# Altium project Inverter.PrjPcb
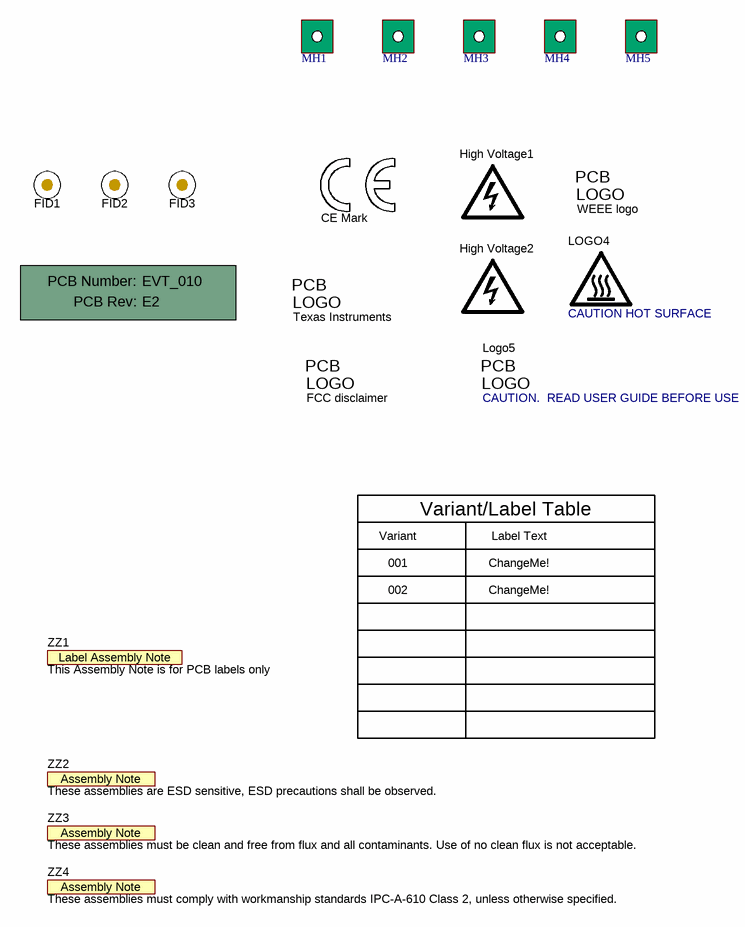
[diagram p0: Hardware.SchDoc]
TID: N/A; TechSupport: http://www.ti.com/support; SCH_Rev: E2; PRJ_Title: SiC Inverter Main Board; PRJ_Number: EVT_010; PRJ_Engineer: Ramesh Ramamoorthy; PRJ_Customer: EV Traction; PCB_Rev: E2; PCB_Layout: Ramesh Ramamoorthy; CopyrightYear: 2020
2 sheets, 92 parts. Net scope: global (net labels, ports and power ports of the same name join across sheets).
Board file: inverter_r7.PcbDoc
Sheets:
  Hardware.SchDoc
  inverter_r5.SchDoc

## Sheet Hardware.SchDoc
size 431 x 279 mm; Date: Not shown in title block; ApprovedBy: Not shown in title block; CheckedBy: Not shown in title block; Author: Not shown in title block; CompanyName: Not shown in title block; Engineer: Not shown in title block; Organization: Not shown in title block; Address1: Not shown in title block; Address2: Not shown in title block; Address3: Not shown in title block; Address4: Not shown in title block; DocumentNumber: 3; Revision: Use project parameter SCH_Rev; SheetNumber: 3; SheetTotal: 3; PageSetup: Record=PageOptions¦CenterHorizontal=True¦CenterVertical=True¦PrintScale=1.00¦XCorrection=1.00¦YCorrection=1.00¦PrintKind=0¦BorderSize=5000000¦LeftOffset=0¦BottomOffset=0¦Orientation=2¦PaperLength=1000¦PaperWidth=1000¦Scale=100¦PaperSource=15¦PrintQuality=600¦MediaType=1¦DitherType=10¦PaperKind=Letter¦PrintScaleMode=1

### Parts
!PCB1  Printed Circuit Board  (value not drawn)  (mechanical)
FID1  Fiducial  [Fiducial10-20]  (value not drawn)
FID2  Fiducial  [Fiducial10-20]  (value not drawn)
FID3  Fiducial  [Fiducial10-20]  (value not drawn)
High_Voltage1  DANGER HIGH VOLTAGE  [IEC_HighVoltage_Small]  (value not drawn)  (no BOM)
High_Voltage2  DANGER HIGH VOLTAGE  [IEC_HighVoltage_Small]  (value not drawn)  (no BOM)
Logo1  Texas Instruments  [TI_Stacked_Overlay_Medium]  (no BOM)
Logo2  CE Mark  [CE_Mark_5mm]  (no BOM)
Logo3  WEEE logo  [WEEE_Minimum]  (no BOM)
LOGO4  CAUTION HOT SURFACE  [IEC_HotSurface_Small]  (no BOM)
Logo5  CAUTION.  READ USER GUIDE BEFORE USE  [IEC_Caution_Small]  (no BOM)
Logo6  FCC disclaimer  [FCC_disclaimer]  (no BOM)
MH1  MTG_NoPads  [MTG_159mil]  (value not drawn)  (no BOM)
MH2  MTG_NoPads  [MTG_159mil]  (value not drawn)  (no BOM)
MH3  MTG_NoPads  [MTG_159mil]  (value not drawn)  (no BOM)
MH4  MTG_NoPads  [MTG_159mil]  (value not drawn)  (no BOM)
MH5  MTG_NoPads  [MTG_159mil]  (value not drawn)  (no BOM)
ZZ1  This Assembly Note is for PCB labels only  [AssemblyNoteLabel]  (no BOM)
ZZ2  These assemblies are ESD sensitive, ESD precautions shall be observed.  [AssemblyNote]  (no BOM)
ZZ3  These assemblies must be clean and free from flux and all contaminants. Use of no clean flux is not acceptable.  [AssemblyNote]  (no BOM)
ZZ4  These assemblies must comply with workmanship standards IPC-A-610 Class 2, unless otherwise specified.  [AssemblyNote]  (no BOM)

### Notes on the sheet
- Variant
- Variant/Label Table
- Label Text
- 001
- 002
- ChangeMe!

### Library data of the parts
!PCB1 = CMP-0003618-2: Manufacturer: Any; PartNumber: EVT_010
FID1-FID3 = CMP-0077181-1: Fiducial mark.  There is nothing to buy or mount.
High_Voltage1 High_Voltage2 = CMP-0074835-1: IEC 61010-1 High Voltage Warning; SymbolCreator: a0412235
Logo1 = CMP-0074838-1: Texas Instrument Corporate Signature; SymbolCreator: a0412235; Lib Reference: TI_Logo; Library Reference: Logo
Logo2 = CMP-0074844-1: SymbolCreator: a0412235
Logo3 = CMP-0074769-1
LOGO4 = CMP-0074837-1: IEC 61010-1 Hot Surface Warning; SymbolCreator: a0412235
Logo5 = CMP-0074836-1: IEC 61010-1 Caution Warning; SymbolCreator: a0412235; Lib Reference: IEC_Caution
Logo6 = CMP-0074847-1: FCC_disclaimer; Library Reference: Logo
MH1-MH5 = CMP-0078424-2: PCB Mounting Hole, No Pad; Manufacturer: Any; Key: Mounting Hole (non-standard) No Pad
ZZ1 = CMP-0003616-3
ZZ2 = CMP-0077236-1
ZZ3 = CMP-0077237-1
ZZ4 = CMP-0077238-1

## Sheet inverter_r5.SchDoc
size 431 x 279 mm; Date: Not shown in title block; ApprovedBy: Not shown in title block; CheckedBy: Not shown in title block; Author: Not shown in title block; CompanyName: Not shown in title block; Engineer: Not shown in title block; Organization: Not shown in title block; Address1: Not shown in title block; Address2: Not shown in title block; Address3: Not shown in title block; Address4: Not shown in title block; DocumentNumber: 2; Revision: Use project parameter SCH_Rev; SheetNumber: 2; SheetTotal: 3; PageSetup: Record=PageOptions¦CenterHorizontal=True¦CenterVertical=True¦PrintScale=1.00¦XCorrection=1.00¦YCorrection=1.00¦PrintKind=0¦BorderSize=5000000¦LeftOffset=0¦BottomOffset=0¦Orientation=2¦PaperLength=1000¦PaperWidth=1000¦Scale=100¦PaperSource=15¦PrintQuality=600¦MediaType=1¦DitherType=10¦PaperKind=Letter¦PrintScaleMode=1
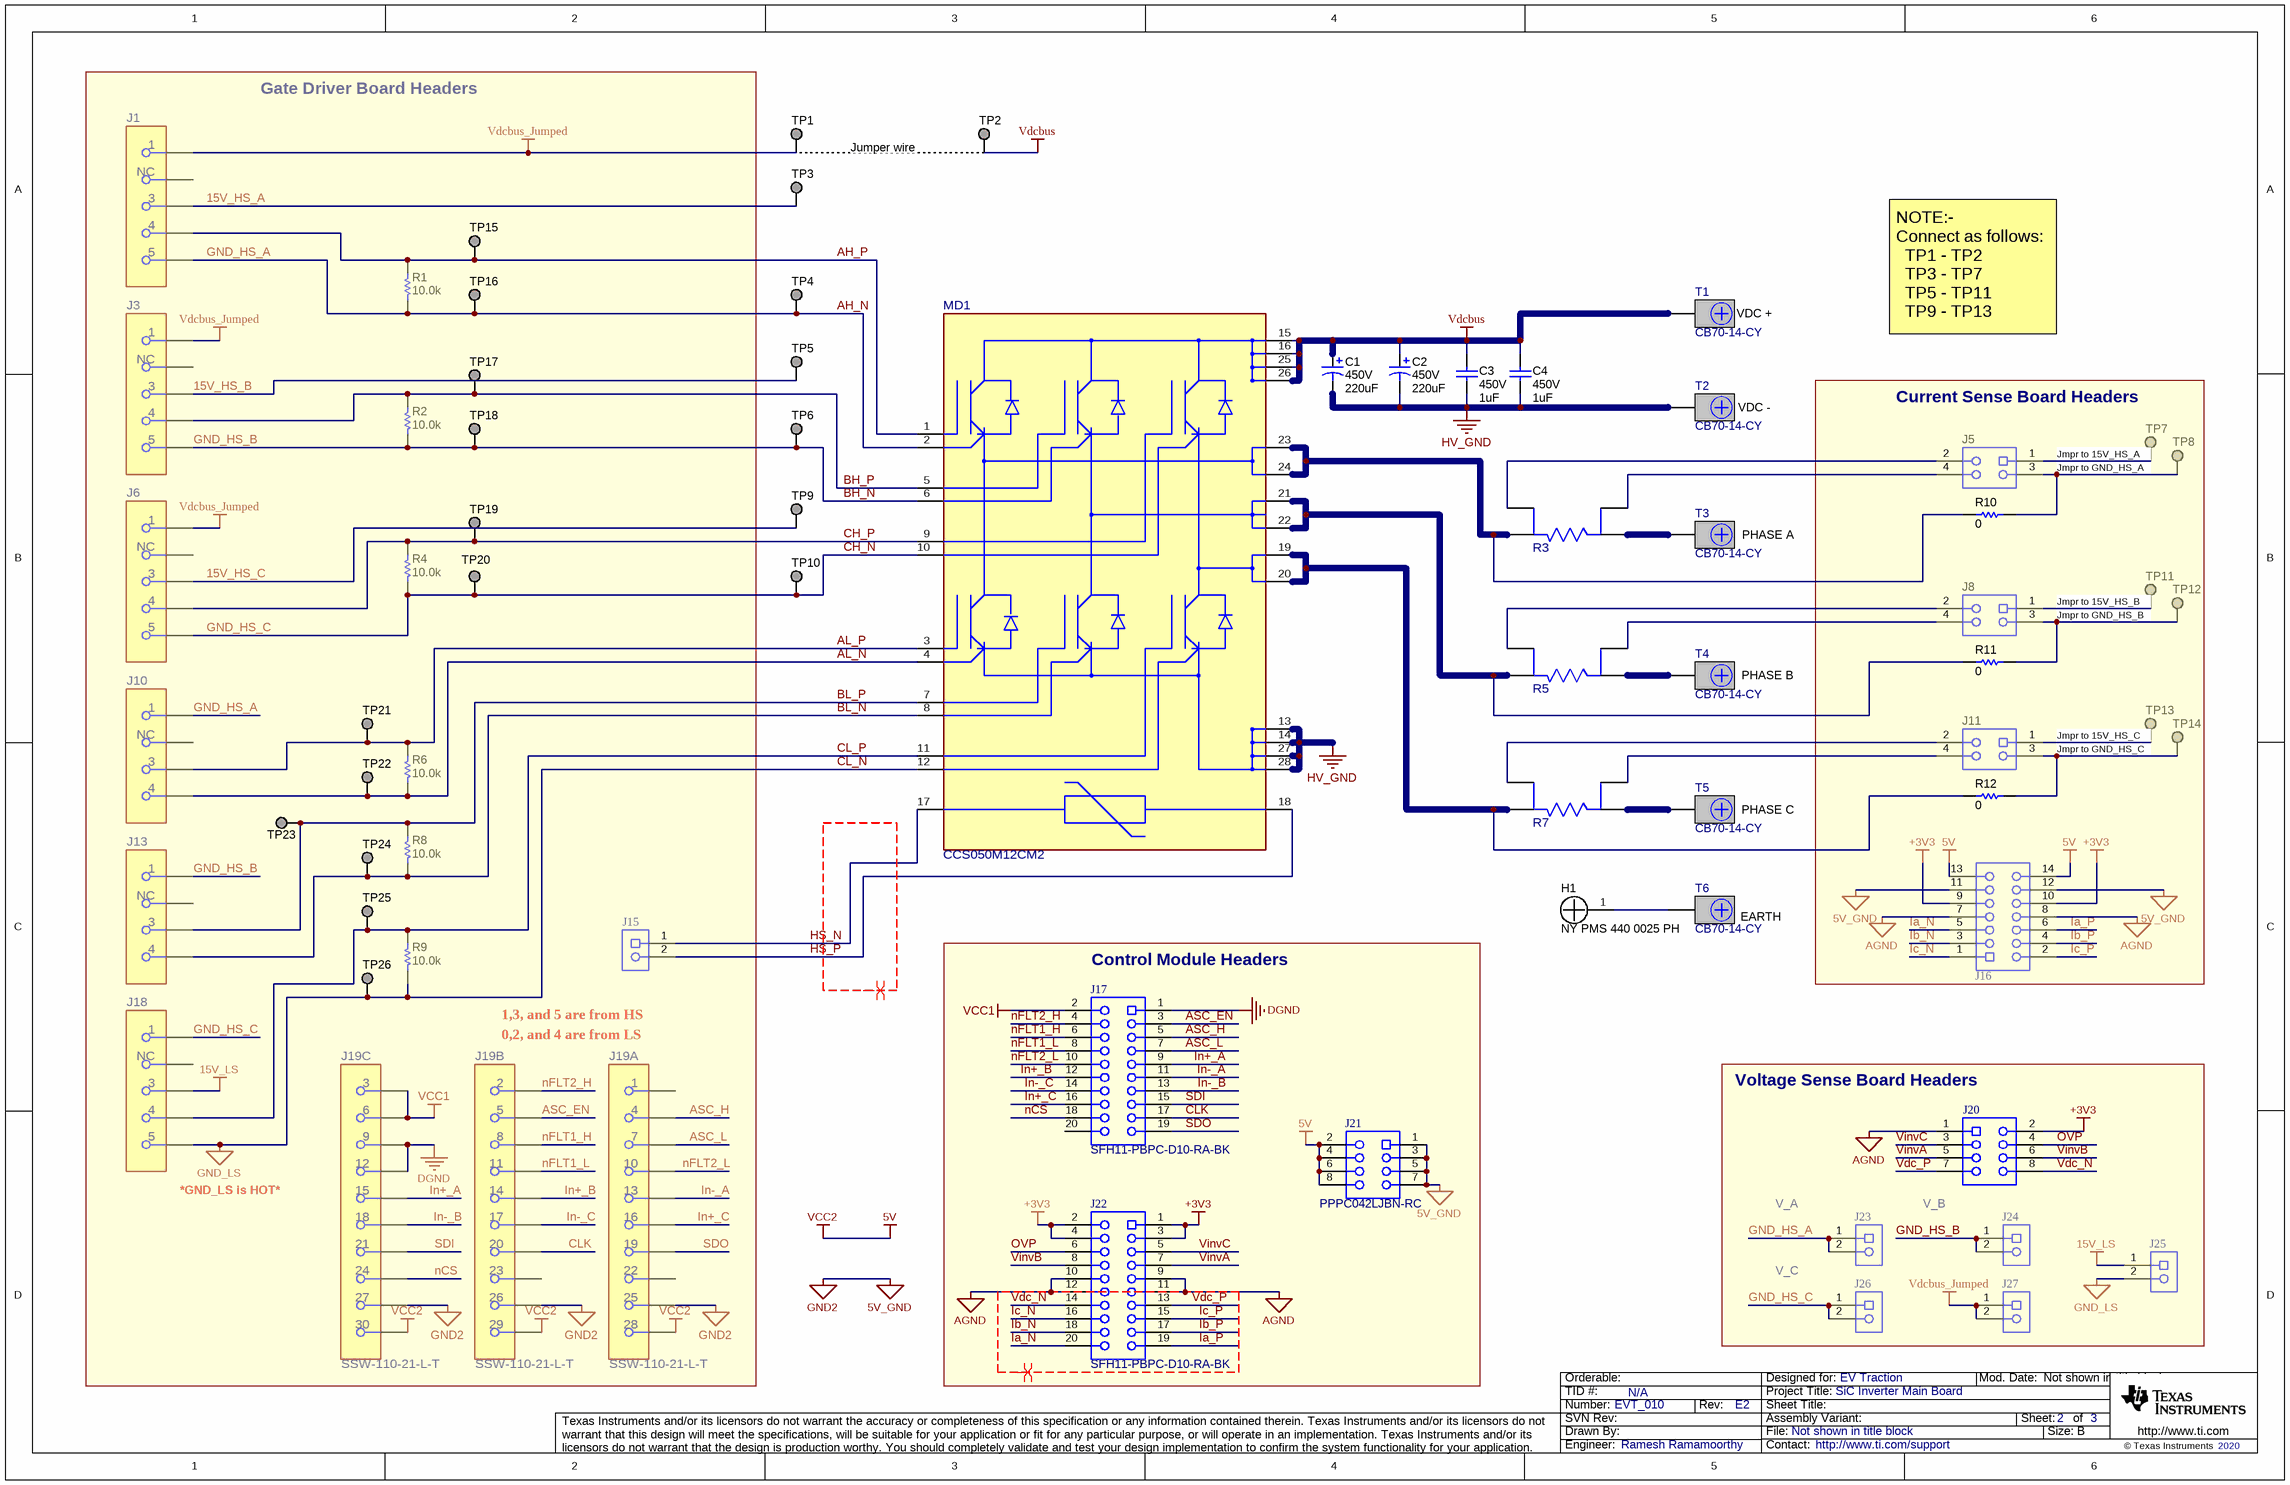
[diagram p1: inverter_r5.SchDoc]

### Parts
C1  VDC_V: 450V  ValueDisplayed: 220uF  [Nichicon_2500x4000_Snap]  (hidden comment: LLS2W221MELA)
C2  VDC_V: 450V  ValueDisplayed: 220uF  [Nichicon_2500x4000_Snap]  (hidden comment: LLS2W221MELA)
C3  VDC_V: 450V  ValueDisplayed: 1uF  [MPK_1800x950]  (hidden comment: 450MPK105J)
C4  VDC_V: 450V  ValueDisplayed: 1uF  [MPK_1800x950]  (hidden comment: 450MPK105J)
H1  NY PMS 440 0025 PH  [NY PMS 440 0025 PH]
J1  SSW-105-01-G-S-002  [FP-SSW-105-01-G-S-002_HDR4-MFG]  (value not drawn)
J3  SSW-105-01-G-S-002  [FP-SSW-105-01-G-S-002_HDR4-MFG]  (value not drawn)
J5  5-534206-2  [CONN_534206-2]  (value not drawn)
J6  SSW-105-01-G-S-002  [FP-SSW-105-01-G-S-002_HDR4-MFG]  (value not drawn)
J8  5-534206-2  [CONN_534206-2]  (value not drawn)
J10  SSW-104-01-G-S-002  [FP-SSW-104-01-G-S-002_HDR4-MFG]  (value not drawn)
J11  5-534206-2  [CONN_534206-2]  (value not drawn)
J13  SSW-104-01-G-S-002  [FP-SSW-104-01-G-S-002_HDR4-MFG]  (value not drawn)
J15  5-534206-1  [CONN_534206-1]  (value not drawn)
J16  PPPC072LFBN-RC  [Sullins_xPxC072LFBN-RC]  (value not drawn)
J17  SFH11-PBPC-D10-RA-BK  [Sullins_SFH11-xxxC-D10-RA]
J18  SSW-105-01-G-S-002  [FP-SSW-105-01-G-S-002_HDR4-MFG]  (value not drawn)
J19  SSW-110-21-L-T  [FP-SSW-110-21-L-T_HDR30-MFG]  (parts A,B,C of 3)
J20  PPPC042LFBN-RC  [CONN_PPPC042LFBN-RC]  (value not drawn)
J21  PPPC042LJBN-RC  [CONN_PPPC042LJBN-RC]
J22  SFH11-PBPC-D10-RA-BK  [Sullins_SFH11-xxxC-D10-RA]
J23  5-534206-1  [CONN_534206-1]  (value not drawn)
J24  5-534206-1  [CONN_534206-1]  (value not drawn)
J25  5-534206-1  [CONN_534206-1]  (value not drawn)
J26  5-534206-1  [CONN_534206-1]  (value not drawn)
J27  5-534206-1  [CONN_534206-1]  (value not drawn)
MD1  CCS050M12CM2  [FP-CCS050M12CM2_PTH_MODULE_107MM5_45MM-MFG]
R1  ValueDisplayed: 10.0k  [0603]  (hidden comment: CRCW060310K0FKEA)
R2  ValueDisplayed: 10.0k  [0603]  (hidden comment: CRCW060310K0FKEA)
R3  CSS4J-4026R-L500F  [FP-CSS4J-4026R-L500F_4026-MFG]  (value not drawn)
R4  ValueDisplayed: 10.0k  [0603]  (hidden comment: CRCW060310K0FKEA)
R5  CSS4J-4026R-L500F  [FP-CSS4J-4026R-L500F_4026-MFG]  (value not drawn)
R6  ValueDisplayed: 10.0k  [0603]  (hidden comment: CRCW060310K0FKEA)
R7  CSS4J-4026R-L500F  [FP-CSS4J-4026R-L500F_4026-MFG]  (value not drawn)
R8  ValueDisplayed: 10.0k  [0603]  (hidden comment: CRCW060310K0FKEA)
R9  ValueDisplayed: 10.0k  [0603]  (hidden comment: CRCW060310K0FKEA)
R10  ValueDisplayed: 0  [0805_HV]  (hidden comment: ERJ-6GEY0R00V)
R11  ValueDisplayed: 0  [0805_HV]  (hidden comment: ERJ-6GEY0R00V)
R12  ValueDisplayed: 0  [0805_HV]  (hidden comment: ERJ-6GEY0R00V)
T1  CB70-14-CY  [CB70-14-CY]
T2  CB70-14-CY  [CB70-14-CY]
T3  CB70-14-CY  [CB70-14-CY]
T4  CB70-14-CY  [CB70-14-CY]
T5  CB70-14-CY  [CB70-14-CY]
T6  CB70-14-CY  [CB70-14-CY]
TP1  TP_H0.45P0.75  [TP_H045P075]  (value not drawn)  (no BOM)
TP2  TP_H0.45P0.75  [TP_H045P075]  (value not drawn)  (no BOM)
TP3  TP_H0.45P0.75  [TP_H045P075]  (value not drawn)  (no BOM)
TP4  TP_H0.45P0.75  [TP_H045P075]  (value not drawn)  (no BOM)
TP5  TP_H0.45P0.75  [TP_H045P075]  (value not drawn)  (no BOM)
TP6  TP_H0.45P0.75  [TP_H045P075]  (value not drawn)  (no BOM)
TP7  TP_H0.45P0.75  [TP_H045P075]  (value not drawn)  (no BOM)
TP8  TP_H0.45P0.75  [TP_H045P075]  (value not drawn)  (no BOM)
TP9  TP_H0.45P0.75  [TP_H045P075]  (value not drawn)  (no BOM)
TP10  TP_H0.45P0.75  [TP_H045P075]  (value not drawn)  (no BOM)
TP11  TP_H0.45P0.75  [TP_H045P075]  (value not drawn)  (no BOM)
TP12  TP_H0.45P0.75  [TP_H045P075]  (value not drawn)  (no BOM)
TP13  TP_H0.45P0.75  [TP_H045P075]  (value not drawn)  (no BOM)
TP14  TP_H0.45P0.75  [TP_H045P075]  (value not drawn)  (no BOM)
TP15  TESTPOINT  [TESTPOINT]  (value not drawn)  (no BOM)
TP16  TESTPOINT  [TESTPOINT]  (value not drawn)  (no BOM)
TP17  TESTPOINT  [TESTPOINT]  (value not drawn)  (no BOM)
TP18  TESTPOINT  [TESTPOINT]  (value not drawn)  (no BOM)
TP19  TESTPOINT  [TESTPOINT]  (value not drawn)  (no BOM)
TP20  TESTPOINT  [TESTPOINT]  (value not drawn)  (no BOM)
TP21  TESTPOINT  [TESTPOINT]  (value not drawn)  (no BOM)
TP22  TESTPOINT  [TESTPOINT]  (value not drawn)  (no BOM)
TP23  TESTPOINT  [TESTPOINT]  (value not drawn)  (no BOM)
TP24  TESTPOINT  [TESTPOINT]  (value not drawn)  (no BOM)
TP25  TESTPOINT  [TESTPOINT]  (value not drawn)  (no BOM)
TP26  TESTPOINT  [TESTPOINT]  (value not drawn)  (no BOM)

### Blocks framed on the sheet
Gate Driver Board Headers: J1 J3 J6 J10 J13 J15 J18 J19 R1 R2 R4 R6 R8 R9 TP15-TP26
Current Sense Board Headers: J5 J8 J11 J16 R10-R12 TP7 TP8 TP11-TP14
Control Module Headers: J17 J21 J22
Voltage Sense Board Headers: J20 J23-J27

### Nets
5V: J16.13 J16.14 J19.28 J19.29 J19.30 J21.2 J21.4 J21.6 J21.8  [also labelled VCC2]
5V_GND: J16.11 J16.12 J19.25 J19.26 J19.27 J21.1 J21.3 J21.5 J21.7  [also labelled GND2]
15V_LS: J18.3 J25.1
+3V3: J16.9 J16.10 J20.2 J22.1 J22.2 J22.3 J22.4
AGND: J16.7 J16.8 J20.1 J22.9 J22.10 J22.11 J22.12
CL_N: J18.5 J25.2 MD1.12(6_DRIVER_SOURCE) R9.2 TP26.1  [also labelled GND_LS]
DGND: J17.1 J19.9 J19.12
HV_GND: C1.2(-) C2.2(-) C3.2 C4.2 MD1.13(2/4/6_POWER_SOURCE) MD1.14(2/4/6_POWER_SOURCE) MD1.27(2/4/6_POWER_SOURCE) MD1.28(2/4/6_POWER_SOURCE) T2.1
VCC1: J17.2 J19.3 J19.6
Vdcbus: C1.1(+) C2.1(+) C3.1 C4.1 MD1.15(1/3/5_DRAIN) MD1.16(1/3/5_DRAIN) MD1.25(1/3/5_DRAIN) MD1.26(1/3/5_DRAIN) T1.1 TP2.1
Vdcbus_Jumped: J1.1 J3.1 J6.1 J27.1 J27.2 TP1.1
15V_HS_A: J1.3 TP3.1
15V_HS_B: J3.3 TP5.1
15V_HS_C: J6.3 TP9.1
AH_N: J1.5 J10.1 J23.1 J23.2 MD1.2(1_DRIVER_SOURCE) R1.2 TP4.1 TP16.1  [also labelled GND_HS_A]
AH_P: J1.4 MD1.1(1_GATE) R1.1 TP15.1
AL_N: J10.4 MD1.4(2_DRIVER_SOURCE) R6.2 TP22.1
AL_P: J10.3 MD1.3(2_GATE) R6.1 TP21.1
ASC_EN: J17.3 J19.5
ASC_H: J17.5 J19.4
ASC_L: J17.7 J19.7
BH_N: J3.5 J13.1 J24.1 J24.2 MD1.6(3_DRIVER_SOURCE) R2.2 TP6.1 TP18.1  [also labelled GND_HS_B]
BH_P: J3.4 MD1.5(3_GATE) R2.1 TP17.1
BL_N: J13.4 MD1.8(4_DRIVER_SOURCE) R8.2 TP24.1
BL_P: J13.3 MD1.7(4_GATE) R8.1 TP23.1
CH_N: J6.5 J18.1 J26.1 J26.2 MD1.10(5_DRIVER_SOURCE) R4.2 TP10.1 TP20.1  [also labelled GND_HS_C]
CH_P: J6.4 MD1.9(5_GATE) R4.1 TP19.1
CL_P: J18.4 MD1.11(6_GATE) R9.1 TP25.1
CLK: J17.17 J19.20
HS_N: J15.1 MD1.17(1_NTC)
HS_P: J15.2 MD1.18(2_NTC)
Ia_N: J16.5 J22.20
Ia_P: J16.6 J22.19
Ib_N: J16.3 J22.18
Ib_P: J16.4 J22.17
Ic_N: J16.1 J22.16
Ic_P: J16.2 J22.15
In+_A: J17.9 J19.15
In+_B: J17.12 J19.14
In+_C: J17.16 J19.16
In-_A: J17.11 J19.13
In-_B: J17.13 J19.18
In-_C: J17.14 J19.17
nCS: J17.18 J19.24
nFLT1_H: J17.6 J19.8
nFLT1_L: J17.8 J19.11
nFLT2_H: J17.4 J19.2
nFLT2_L: J17.10 J19.10
OVP: J20.4 J22.6
SDI: J17.15 J19.21
SDO: J17.19 J19.19
Vdc_N: J20.8 J22.14
Vdc_P: J20.7 J22.13
VinvA: J20.5 J22.7
VinvB: J20.6 J22.8
VinvC: J20.3 J22.5
NetH1_1: H1.1 T6.1
NetJ5_1: J5.1 TP7.1
NetJ5_2: J5.2 R3.2(2_SENSE)
NetJ5_3: J5.3 R10.2 TP8.1
NetJ5_4: J5.4 R3.1(1_SENSE)
NetJ8_1: J8.1 TP11.1
NetJ8_2: J8.2 R5.2(2_SENSE)
NetJ8_3: J8.3 R11.2 TP12.1
NetJ8_4: J8.4 R5.1(1_SENSE)
NetJ11_1: J11.1 TP13.1
NetJ11_2: J11.2 R7.2(2_SENSE)
NetJ11_3: J11.3 R12.2 TP14.1
NetJ11_4: J11.4 R7.1(1_SENSE)
NetMD1_19: MD1.19(5_POWER_SOURCE/6_DRAIN) MD1.20(5_POWER_SOURCE/6_DRAIN) R7.4(2_FORCE) R12.1
NetMD1_21: MD1.21(3_POWER_SOURCE/4_DRAIN) MD1.22(3_POWER_SOURCE/4_DRAIN) R5.4(2_FORCE) R11.1
NetMD1_23: MD1.23(1_POWER_SOURCE/2_DRAIN) MD1.24(1_POWER_SOURCE/2_DRAIN) R3.4(2_FORCE) R10.1
NetR3_3: R3.3(1_FORCE) T3.1
NetR5_3: R5.3(1_FORCE) T4.1
NetR7_3: R7.3(1_FORCE) T5.1

Not connected (* = marked no-connect by the designer): J1 2(NC); J3 2(NC); J6 2(NC); J10 2(NC); J13 2(NC); J17 20; J18 2(NC); J19 1 22 23

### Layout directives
differential pair: (no net found under the mark), Ia_N, Ia_P, Ib_N, Ib_P, Ic_N, Ic_P, Vdc_N, Vdc_P

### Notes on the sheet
- Jumper wire
- (near T1) VDC +
- NOTE:-
  Connect as follows:
  TP1 - TP2
  TP3 - TP7
  TP5 - TP11
  TP9 - TP13
- (near T2) VDC -
- (near TP7) Jmpr to 15V_HS_A
- (near TP7) Jmpr to GND_HS_A
- (near T3) PHASE A
- (near TP11) Jmpr to 15V_HS_B
- (near TP11) Jmpr to GND_HS_B
- (near T4) PHASE B
- (near TP13) Jmpr to 15V_HS_C
- (near TP13) Jmpr to GND_HS_C
- (near T5) PHASE C
- (near T6) EARTH
- 1,3, and 5 are from HS
- (near J19) 0,2, and 4 are from LS
- (near J18) *GND_LS is HOT*
- V_A
- (near J20) V_B
- V_C

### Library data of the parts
C1 C2 = CMP-0010109-2: CAP, AL, 220 uF, 450 V, +/- 20%, TH; Manufacturer: Nichicon; TaMin_C: -25°C; Polarized: Y; SizeAreaWB_mm2: 729; Value1: Unknown; U/M: EA; Value: 220uF; TaMax_C: 85°C; SizeZ_mm: 42; SizeX_mm: 25; Cap_Case: 25x40mm; SizeArea_mm2: 625; CompType: Capacitor; AEC Qualified: N; Cap_F: 220µF; IRMS_A: 1.59A; AEC Category: Q200
C3 C4 = CMP-0012307-1: CAP, Film, 1 uF, 450 V, +/- 5%, TH; Manufacturer: Rubycon; TaMin_C: -40°C; Polarized: N; Value1: Unknown; U/M: EA; Value: 1uF; TaMax_C: 105°C; Cap_Case: 18x9.5mm; Cap_F: 1µF; AEC Category: Q200
H1 = CMP-0003617-1: Machine Screw, Round, #4-40 x 1/4, Nylon, Philips panhead; Manufacturer: B&F Fastener Supply; CompType: Hardware
J1 J3 J6 J18 = CMP-0088431-1: Conn Socket Strip SKT 5 POS 2.54mm Solder ST Thru-Hole; Manufacturer: Samtec; SizeZ_mm: 8.64mm; Voltage_V: 655V; AEC Qualified: No; ContactFinish: Gold,Nickel; Conn Orientation: Vertical; Current_A: 4.7A; Conn Gender: Female; Row_Count: 1; Is Female: yes
J5 J8 J11 = CMP-0054835-1: Connector, Receptacle, 100mil, 2x2, Gold plated, TH; Manufacturer: TE Connectivity; CT: FALSE
J10 J13 = CMP-0088428-1: 4 Position Receptacle Connector Through Hole; Manufacturer: Samtec; Voltage_V: 655V; SizeZ_mm: 8.64mm; Is Female: yes; Conn Orientation: Vertical; AEC Qualified: No; ContactFinish: Gold,Nickel; DUT-Pitch_mm: 2.54mm; Conn Gender: Female; Row_Count: 1; Current_A: 4.7A
J15 J23-J27 = CMP-0054836-1: Connector, Receptacle, 100mil, 2x1, Gold plated, TH; Manufacturer: TE Connectivity; CNHeader: FALSE; Green_Lifecycle: Active; Green_REACh: Passed
J16 = CMP-0054669-1: Receptacle, 2.54mm, 7x2, Gold, TH; Manufacturer: Sullins Connector Solutions; CNHeader: FALSE; Gender: Female; CompType: Socket Strip; Row_Count: 2; RowSpacing_mm: 2.54; CT: TRUE
J17 J22 = CMP-0074634-1: Receptacle, 2.54mm, 10x2, Gold, R/A, TH; Manufacturer: Sullins Connector Solutions; CNHeader: False; Current_A: 3A; Gender: Female; Voltage_V: 1kV; CompType: Socket Strip; Row_Count: 2; Pitch_mm: 2.54; CT: True; Cert_UL: Y
J19 = CMP-0088699-1: Connector, Header, 30 Position Receptacle, Through Hole; Manufacturer: Samtec; DUT-Pitch_mm: 2.54mm; AEC Qualified: No; Voltage_V: 655V; ContactFinish: Gold,Nickel; Conn Orientation: Vertical; Conn Gender: Female; SizeZ_mm: 8.64mm; Row_Count: 3; Is Female: yes; Current_A: 4.7A
J20 = CMP-0054629-2: Connector, Receptacle, 100mil, 4x2, Gold plated, TH; Manufacturer: Sullins Connector Solutions; CompType: Socket Strip
J21 = CMP-0054630-1: Connector, Receptacle, 100mil, 4x2, Gold plated, R/A, TH; Manufacturer: Sullins Connector Solutions; CT: TRUE; CompType: Socket Strip; CNHeader: FALSE
MD1 = CMP-0087815-2: Mosfet Array 6 N-Channel (3-Phase Bridge) 1200V (1.2kV) 87A (Tc) 337W Chassis Mount Module; Manufacturer: Wolfspeed; SizeZ_mm: 17.5mm
R1 R2 R4 R6 R8 R9 = CMP-0021998-4: RES, 10.0 k, 1%, 0.1 W, AEC-Q200 Grade 0, 0603; Manufacturer: Vishay-Dale; Value: 10.0k; Res_ohm: 10k; Value_Code: 10k0; Power_W: 100mW; Value2: 0.1W; VDC_V: 75V; TempCo: 100 ppm/C; SizeArea_mm2: 1.28; SizeX_mm: 1.6; SizeY_mm: 0.8; SizeZ_mm: 1; EIA_Code: E96; AEC Category: Q200; AEC Qualified: Y; AEC Grade: 0
R3 R5 R7 = CMP-0087828-1: RES SMD 500 UOHM 1% 5W 4026; Manufacturer: Bourns; SizeZ_mm: 3.21mm; AEC Qualified: Yes; Res_ohm: 500µ; TempCo: 100ppm/°C; AEC Grade: Grade 0
R10-R12 = CMP-0020616-3: RES, 0, 5%, 0.125 W, AEC-Q200 Grade 0, 0805; Manufacturer: Panasonic; Power_W: 125mW; TempCo: 600 ppm/C; Value_Code: 0000; Value: 0; EIA_Code: E24; SizeX_mm: 2; SizeY_mm: 1.25; SizeZ_mm: 1.45; Value2: 0.125W; SizeArea_mm2: 2.5; AEC Qualified: Y; VDC_V: 150V; AEC Category: Q200; SizeAreaWB_mm2: 6.75
T1-T6 = CMP-0055443-2: Terminal 90A Lug; Manufacturer: Panduit; Green_Lifecycle: Not Set; Cert_CULUS: Y; Green_REACh: Incomplete; Voltage_V: 600V; CompType: Screw Terminal; ContactFinish: Copper
TP1-TP14 = CMP-0003719-1: Testpoint; Manufacturer: Texas Instruments; CompType: Pad
TP15-TP26 = CMP-0078143-3: TEST POINT.  No entry in BOM.

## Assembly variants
001: not fitted FID1 FID2 FID3 R10 R11 R12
